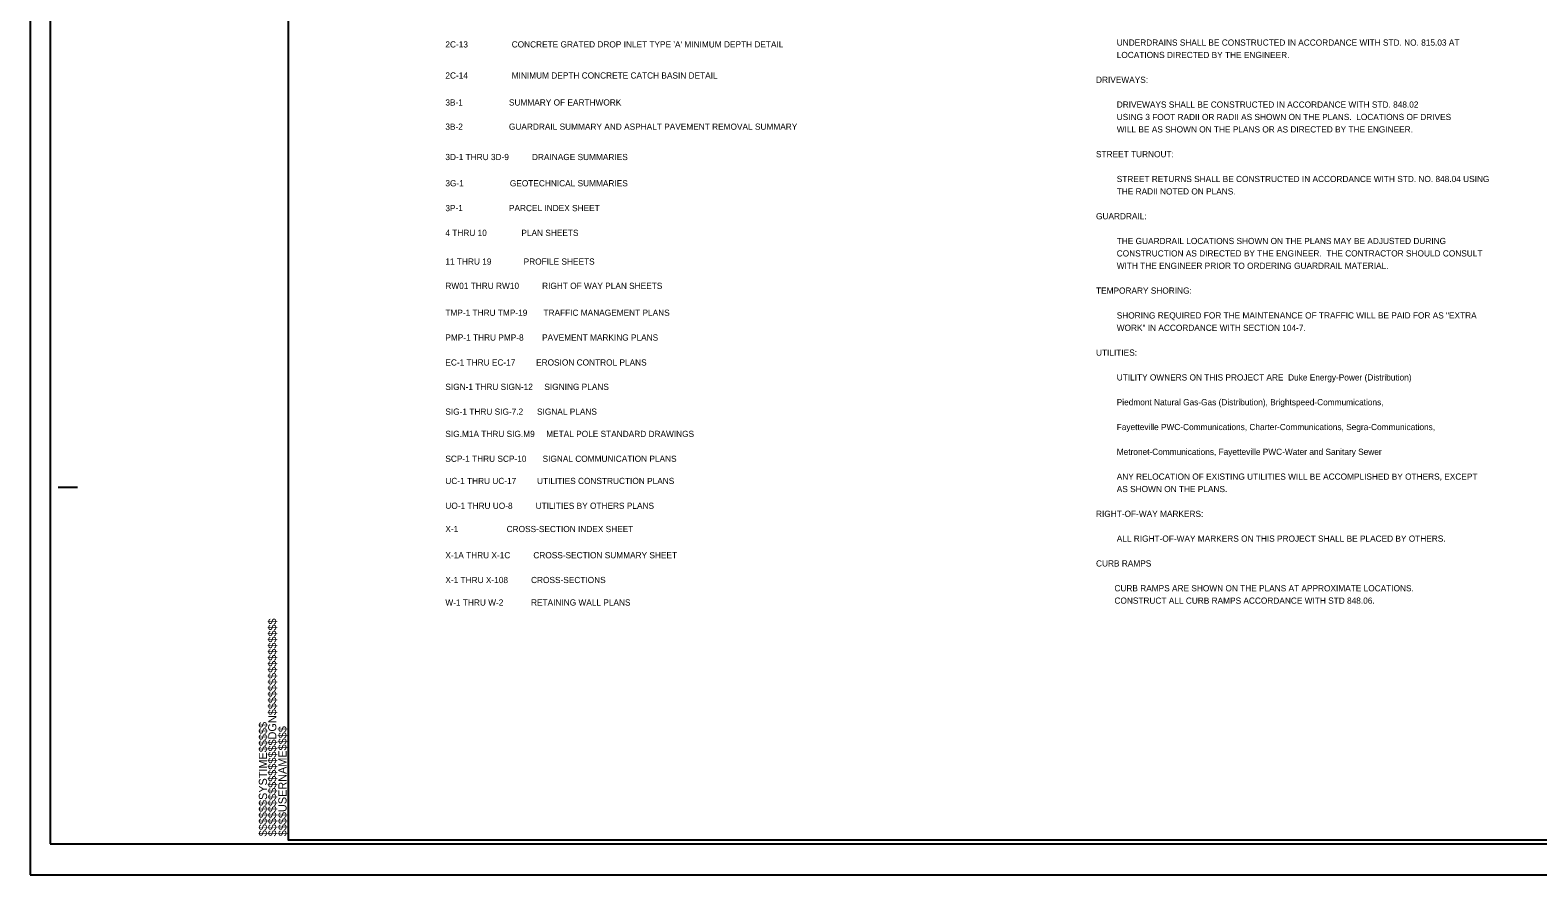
# Model space of a CAD drawing. Extents: x 1537922 to 1539606, y 409903 to 410998.
# Drawn here: x 1537922 to 1538895, y 409903 to 410448 of the extents above; entities that cross this region are included whole.
import ezdxf

# ---------------------------------------------------------------- set-up
doc = ezdxf.new("R2010")
doc.units = 0
for name, color, linetype in [('Old_Level_1', 7, 'Continuous'), ('Sheet Cutting Line CELL', 7, 'Continuous'), ('Sheet Plan CELL', 7, 'Continuous'), ('Sheet Plot Border Inside CELL', 7, 'Continuous'), ('Sheet Plot Border Outside CELL', 7, 'Continuous')]:
    doc.layers.add(name, color=color, linetype=linetype)

msp = doc.modelspace()

# ---------------------------------------------------------------- linework, layer by layer
at = {"layer": 'Sheet Cutting Line CELL'}
for p, q in [((1537922.37, 410998.35), (1537922.37, 409903.35)), ((1537922.37, 409903.35), (1539605.87, 409903.35))]:
    msp.add_line(p, q, dxfattribs=at)
at = {"layer": 'Sheet Plan CELL'}
for p, q in [((1537940.37, 410153.35), (1537952.87, 410153.35)), ((1538088.87, 409925.85), (1538088.87, 409925.85))]:
    msp.add_line(p, q, dxfattribs=at)
msp.add_lwpolyline([(1539588.87, 410975.85), (1538088.87, 410975.85), (1538088.87, 409925.85), (1539588.87, 409925.85)], close=True, dxfattribs=at)
at = {"layer": 'Sheet Plot Border Inside CELL'}
msp.add_lwpolyline([(1537935.37, 409923.35), (1539601.37, 409923.35), (1539601.37, 410978.35), (1537935.37, 410978.35)], close=True, dxfattribs=at)
at = {"layer": 'Sheet Plot Border Outside CELL'}
msp.add_lwpolyline([(1537922.37, 409903.35), (1539605.87, 409903.35), (1539605.87, 410998.35), (1537922.37, 410998.35)], close=True, dxfattribs=at)

# ---------------------------------------------------------------- texts
at = {"layer": 'Old_Level_1'}
for s, p in [('         UNDERDRAINS SHALL BE CONSTRUCTED IN ACCORDANCE WITH STD. NO. 815.03 AT ', (1538610.1, 410438.24)), ("2C-13                   CONCRETE GRATED DROP INLET TYPE 'A' MINIMUM DEPTH DETAIL", (1538190.28, 410437.07)), ('         LOCATIONS DIRECTED BY THE ENGINEER.  ', (1538610.1, 410430.24)), ('2C-14                   MINIMUM DEPTH CONCRETE CATCH BASIN DETAIL', (1538190.28, 410417.01)), ('DRIVEWAYS:  ', (1538610.1, 410414.24)), ('3B-1                    SUMMARY OF EARTHWORK ', (1538190.28, 410399.62)), ('         USING 3 FOOT RADII OR RADII AS SHOWN ON THE PLANS.  LOCATIONS OF DRIVES', (1538610.1, 410390.24)), ('         DRIVEWAYS SHALL BE CONSTRUCTED IN ACCORDANCE WITH STD. 848.02', (1538610.1, 410398.24)), ('3B-2                    GUARDRAIL SUMMARY AND ASPHALT PAVEMENT REMOVAL SUMMARY', (1538190.28, 410383.99)), ('         WILL BE AS SHOWN ON THE PLANS OR AS DIRECTED BY THE ENGINEER.  ', (1538610.1, 410382.24)), ('3D-1 THRU 3D-9          DRAINAGE SUMMARIES', (1538190.28, 410364.42)), ('STREET TURNOUT:  ', (1538610.1, 410366.24)), ('         STREET RETURNS SHALL BE CONSTRUCTED IN ACCORDANCE WITH STD. NO. 848.04 USING ', (1538610.1, 410350.24)), ('3G-1                    GEOTECHNICAL SUMMARIES', (1538190.28, 410347.48)), ('         THE RADII NOTED ON PLANS.  ', (1538610.1, 410342.24)), ('3P-1                    PARCEL INDEX SHEET', (1538190.28, 410331.48)), ('GUARDRAIL:  ', (1538610.1, 410326.24)), ('4 THRU 10               PLAN SHEETS', (1538190.28, 410315.48)), ('         THE GUARDRAIL LOCATIONS SHOWN ON THE PLANS MAY BE ADJUSTED DURING ', (1538610.1, 410310.24)), ('         CONSTRUCTION AS DIRECTED BY THE ENGINEER.  THE CONTRACTOR SHOULD CONSULT', (1538610.1, 410302.24)), ('11 THRU 19              PROFILE SHEETS', (1538190.28, 410296.97)), ('         WITH THE ENGINEER PRIOR TO ORDERING GUARDRAIL MATERIAL.', (1538610.1, 410294.24)), ('RW01 THRU RW10          RIGHT OF WAY PLAN SHEETS', (1538190.28, 410281.32)), ('TEMPORARY SHORING:  ', (1538610.1, 410278.24)), ('TMP-1 THRU TMP-19       TRAFFIC MANAGEMENT PLANS', (1538190.28, 410263.98)), ('         WORK" IN ACCORDANCE WITH SECTION 104-7.  ', (1538610.1, 410254.24)), ('         SHORING REQUIRED FOR THE MAINTENANCE OF TRAFFIC WILL BE PAID FOR AS "EXTRA ', (1538610.1, 410262.24)), ('PMP-1 THRU PMP-8        PAVEMENT MARKING PLANS', (1538190.28, 410247.98)), ('UTILITIES:  ', (1538610.1, 410238.24)), ('EC-1 THRU EC-17         EROSION CONTROL PLANS', (1538190.28, 410231.88)), ('SIGN-1 THRU SIGN-12     SIGNING PLANS', (1538190.28, 410216.18)), ('         UTILITY OWNERS ON THIS PROJECT ARE  Duke Energy-Power (Distribution)', (1538610.1, 410222.24)), ('         Piedmont Natural Gas-Gas (Distribution), Brightspeed-Commumications,', (1538610.1, 410206.24)), ('SIG-1 THRU SIG-7.2      SIGNAL PLANS', (1538190.28, 410200.16)), ('SIG.M1A THRU SIG.M9     METAL POLE STANDARD DRAWINGS', (1538190.28, 410185.8)), ('         Fayetteville PWC-Communications, Charter-Communications, Segra-Communications,', (1538610.1, 410190.24)), ('SCP-1 THRU SCP-10       SIGNAL COMMUNICATION PLANS', (1538190.28, 410169.78)), ('         Metronet-Communications, Fayetteville PWC-Water and Sanitary Sewer', (1538610.1, 410174.24)), ('UC-1 THRU UC-17         UTILITIES CONSTRUCTION PLANS', (1538190.28, 410155.45)), ('         ANY RELOCATION OF EXISTING UTILITIES WILL BE ACCOMPLISHED BY OTHERS, EXCEPT ', (1538610.1, 410158.24)), ('         AS SHOWN ON THE PLANS.  ', (1538610.1, 410150.24)), ('UO-1 THRU UO-8          UTILITIES BY OTHERS PLANS', (1538190.28, 410139.45)), ('RIGHT-OF-WAY MARKERS:  ', (1538610.1, 410134.24)), ('X-1                     CROSS-SECTION INDEX SHEET', (1538190.28, 410124.44)), ('         ALL RIGHT-OF-WAY MARKERS ON THIS PROJECT SHALL BE PLACED BY OTHERS.  ', (1538610.1, 410118.24)), ('X-1A THRU X-1C          CROSS-SECTION SUMMARY SHEET', (1538190.28, 410107.55)), ('CURB RAMPS', (1538610.1, 410102.24)), ('X-1 THRU X-108          CROSS-SECTIONS', (1538190.28, 410091.55)), ('        CURB RAMPS ARE SHOWN ON THE PLANS AT APPROXIMATE LOCATIONS.', (1538610.1, 410086.24)), ('        CONSTRUCT ALL CURB RAMPS ACCORDANCE WITH STD 848.06.', (1538610.1, 410078.24)), ('W-1 THRU W-2            RETAINING WALL PLANS', (1538190.28, 410077.04))]:
    msp.add_text(s, height=4, dxfattribs=at).set_placement(p)
at = {"layer": 'Sheet Plan CELL'}
for s, p in [('$$$$$$$$$$$$$$$$DGN$$$$$$$$$$$$$$$$', (1538081.22, 409928.21)), ('$$$$$$SYSTIME$$$$$', (1538075.17, 409928.21)), ('$$$$USERNAME$$$$', (1538087.79, 409928.23))]:
    msp.add_text(s, height=5.25, rotation=90, dxfattribs=at).set_placement(p)

doc.saveas('drawing.dxf')
